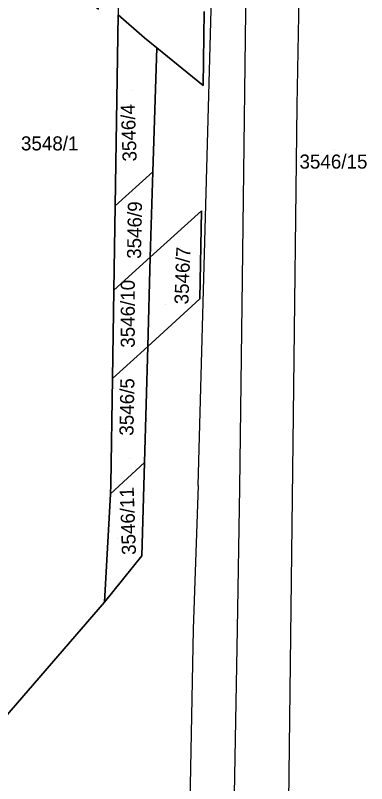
# Model space of a CAD drawing. Extents: x -262657 to -261595, y -1238015 to -1237156.
# Drawn here: x -262399.5 to -262349.5, y -1237502.5 to -1237393.1 of the extents above; entities that cross this region are included whole.
import ezdxf

# ---------------------------------------------------------------- set-up
doc = ezdxf.new("R2010")
doc.units = 0
for name, color, linetype in [('body_kn', 7, 'Continuous'), ('kladpar_druhypozemkov', 7, 'Continuous'), ('kladpar_hranice', 7, 'Continuous'), ('kladpar_parcelnecisla', 7, 'Continuous'), ('kladpar_plochy', 7, 'Continuous'), ('zappar_hrandruhpozemk', 7, 'Continuous')]:
    doc.layers.add(name, color=color, linetype=linetype)

msp = doc.modelspace()

# ---------------------------------------------------------------- linework, layer by layer
at = {"layer": 'body_kn'}
for p, q in [((-262381.12, -1237396.31), (-262381.12, -1237396.31)), ((-262379.37, -1237397.73), (-262379.37, -1237397.73)), ((-262372.75, -1237403.11), (-262372.75, -1237403.11)), ((-262359.45, -1237405.94), (-262359.45, -1237405.94)), ((-262379.95, -1237415.38), (-262379.95, -1237415.38)), ((-262385.29, -1237420.2), (-262385.29, -1237420.2)), ((-262385.29, -1237420.2), (-262385.29, -1237420.2)), ((-262373.03, -1237420.94), (-262373.03, -1237420.94)), ((-262373.03, -1237420.94), (-262373.03, -1237420.94)), ((-262380.3, -1237427.54), (-262380.3, -1237427.54)), ((-262367.23, -1237430.62), (-262367.23, -1237430.62)), ((-262385.47, -1237432.23), (-262385.47, -1237432.23)), ((-262385.47, -1237432.23), (-262385.47, -1237432.23)), ((-262373.24, -1237433.47), (-262373.24, -1237433.47)), ((-262380.66, -1237440.25), (-262380.66, -1237440.25)), ((-262385.66, -1237444.81), (-262385.66, -1237444.81)), ((-262385.66, -1237444.81), (-262385.66, -1237444.81)), ((-262359.99, -1237449.95), (-262359.99, -1237449.95)), ((-262381.13, -1237456.73), (-262381.13, -1237456.73)), ((-262385.89, -1237459.88), (-262385.89, -1237459.88)), ((-262373.47, -1237460.03), (-262373.47, -1237460.03)), ((-262367.62, -1237460.34), (-262367.62, -1237460.34)), ((-262385.96, -1237461.22), (-262385.96, -1237461.22)), ((-262385.96, -1237461.22), (-262385.96, -1237461.22)), ((-262381.51, -1237470.03), (-262381.51, -1237470.03)), ((-262381.51, -1237470.03), (-262381.51, -1237470.03)), ((-262386.8, -1237476.62), (-262386.8, -1237476.62)), ((-262374.19, -1237480.46), (-262374.19, -1237480.46)), ((-262367.94, -1237480.48), (-262367.94, -1237480.48))]:
    msp.add_line(p, q, dxfattribs=at)
at = {"layer": 'kladpar_druhypozemkov'}
for p, q in [((-262382.8, -1237403.75), (-262382.8, -1237403.75)), ((-262394.55, -1237409.41), (-262394.55, -1237409.41)), ((-262354.07, -1237412.18), (-262354.07, -1237412.18)), ((-262383.73, -1237423.31), (-262383.73, -1237423.31)), ((-262378.08, -1237434.31), (-262378.08, -1237434.31)), ((-262385.01, -1237437.34), (-262385.01, -1237437.34)), ((-262383.3, -1237456.22), (-262383.3, -1237456.22)), ((-262384.9, -1237467.61), (-262384.9, -1237467.61))]:
    msp.add_line(p, q, dxfattribs=at)
at = {"layer": 'kladpar_hranice'}
for points in [[(-262406.89, -1237480.27), (-262406.95, -1237476.65), (-262408.32, -1237416.99), (-262409.08, -1237389.58), (-262409.48, -1237365.34), (-262402.63, -1237368.29), (-262402.87, -1237379.16), (-262387.67, -1237392.23), (-262387.29, -1237387.33), (-262385.69, -1237360.96), (-262385.1, -1237341.8), (-262384.08, -1237341.68), (-262384.13, -1237343.92), (-262384.87, -1237393.03), (-262385.29, -1237420.2), (-262385.47, -1237432.23), (-262385.66, -1237444.81), (-262385.89, -1237459.88), (-262385.96, -1237461.22), (-262386.8, -1237476.62), (-262404.36, -1237496.91), (-262406.46, -1237499.34), (-262406.89, -1237480.27)], [(-262404.36, -1237496.91), (-262386.8, -1237476.62), (-262381.51, -1237470.03), (-262381.13, -1237456.73), (-262380.66, -1237440.25), (-262373.24, -1237433.47), (-262373.03, -1237420.94), (-262380.3, -1237427.54), (-262379.95, -1237415.38), (-262379.37, -1237397.73), (-262372.75, -1237403.11), (-262372.62, -1237392.55)], [(-262372.62, -1237392.55), (-262372.75, -1237403.11), (-262379.37, -1237397.73), (-262381.12, -1237396.31), (-262384.87, -1237393.03)], [(-262385.29, -1237420.2), (-262384.87, -1237393.03), (-262381.12, -1237396.31), (-262379.37, -1237397.73), (-262379.95, -1237415.38), (-262385.29, -1237420.2)], [(-262385.47, -1237432.23), (-262385.29, -1237420.2), (-262379.95, -1237415.38), (-262380.3, -1237427.54), (-262385.47, -1237432.23)], [(-262373.03, -1237420.94), (-262373.24, -1237433.47), (-262380.66, -1237440.25), (-262380.3, -1237427.54), (-262373.03, -1237420.94)], [(-262385.66, -1237444.81), (-262385.47, -1237432.23), (-262380.3, -1237427.54), (-262380.66, -1237440.25), (-262385.66, -1237444.81)], [(-262385.96, -1237461.22), (-262385.89, -1237459.88), (-262385.66, -1237444.81), (-262380.66, -1237440.25), (-262381.13, -1237456.73), (-262385.96, -1237461.22)], [(-262381.51, -1237470.03), (-262386.8, -1237476.62), (-262385.96, -1237461.22), (-262381.13, -1237456.73), (-262381.51, -1237470.03)]]:
    msp.add_lwpolyline(points, dxfattribs=at)
at = {"layer": 'kladpar_plochy'}
for points in [[(-262406.89, -1237480.27), (-262406.95, -1237476.65), (-262408.32, -1237416.99), (-262409.08, -1237389.58), (-262409.48, -1237365.34), (-262402.63, -1237368.29), (-262402.87, -1237379.16), (-262387.67, -1237392.23), (-262387.29, -1237387.33), (-262385.69, -1237360.96), (-262385.1, -1237341.8), (-262384.08, -1237341.68), (-262384.13, -1237343.92), (-262384.87, -1237393.03), (-262385.29, -1237420.2), (-262385.47, -1237432.23), (-262385.66, -1237444.81), (-262385.89, -1237459.88), (-262385.96, -1237461.22), (-262386.8, -1237476.62), (-262404.36, -1237496.91), (-262406.46, -1237499.34)], [(-262385.29, -1237420.2), (-262384.87, -1237393.03), (-262381.12, -1237396.31), (-262379.37, -1237397.73), (-262379.95, -1237415.38)], [(-262385.47, -1237432.23), (-262385.29, -1237420.2), (-262379.95, -1237415.38), (-262380.3, -1237427.54)], [(-262373.03, -1237420.94), (-262373.24, -1237433.47), (-262380.66, -1237440.25), (-262380.3, -1237427.54)], [(-262385.66, -1237444.81), (-262385.47, -1237432.23), (-262380.3, -1237427.54), (-262380.66, -1237440.25)], [(-262385.96, -1237461.22), (-262385.89, -1237459.88), (-262385.66, -1237444.81), (-262380.66, -1237440.25), (-262381.13, -1237456.73)], [(-262381.51, -1237470.03), (-262386.8, -1237476.62), (-262385.96, -1237461.22), (-262381.13, -1237456.73)]]:
    msp.add_lwpolyline(points, close=True, dxfattribs=at)
for points in [[(-262404.36, -1237496.91), (-262386.8, -1237476.62), (-262381.51, -1237470.03), (-262381.13, -1237456.73), (-262380.66, -1237440.25), (-262373.24, -1237433.47), (-262373.03, -1237420.94), (-262380.3, -1237427.54), (-262379.95, -1237415.38), (-262379.37, -1237397.73), (-262372.75, -1237403.11), (-262372.62, -1237392.55)], [(-262372.62, -1237392.55), (-262372.75, -1237403.11), (-262379.37, -1237397.73), (-262381.12, -1237396.31), (-262384.87, -1237393.03)]]:
    msp.add_lwpolyline(points, dxfattribs=at)
at = {"layer": 'zappar_hrandruhpozemk'}
for p, q in [((-262358.17, -1237331.61), (-262359.45, -1237405.94)), ((-262373.47, -1237460.03), (-262371.34, -1237381.07)), ((-262359.45, -1237405.94), (-262359.99, -1237449.95)), ((-262367.23, -1237430.62), (-262367.62, -1237460.34)), ((-262359.99, -1237449.95), (-262361.13, -1237544.74))]:
    msp.add_line(p, q, dxfattribs=at)
for points in [[(-262365.91, -1237331.55), (-262366.63, -1237381.11), (-262367.23, -1237430.62)], [(-262373.47, -1237460.03), (-262374.19, -1237480.46), (-262375.15, -1237529.92)], [(-262367.62, -1237460.34), (-262367.94, -1237480.48), (-262368.84, -1237530.07)]]:
    msp.add_lwpolyline(points, dxfattribs=at)

# ---------------------------------------------------------------- texts
at = {"layer": 'kladpar_parcelnecisla'}
for s, rotation, p in [('3546/4', 92, (-262382.22, -1237413.88)), ('3546/9', 89, (-262381.61, -1237427.78)), ('3546/7', 88, (-262374.87, -1237434.27)), ('3546/10', 90, (-262382.5, -1237440.42)), ('3546/5', 89, (-262382.69, -1237452.95)), ('3546/11', 92, (-262382.32, -1237469.88))]:
    msp.add_text(s, height=2, rotation=rotation, dxfattribs=at).set_placement(p)
for s, p in [('3548/1', (-262398.69, -1237412.33)), ('3546/15', (-262359.07, -1237414.92))]:
    msp.add_text(s, height=2, dxfattribs=at).set_placement(p)

doc.saveas('drawing.dxf')
